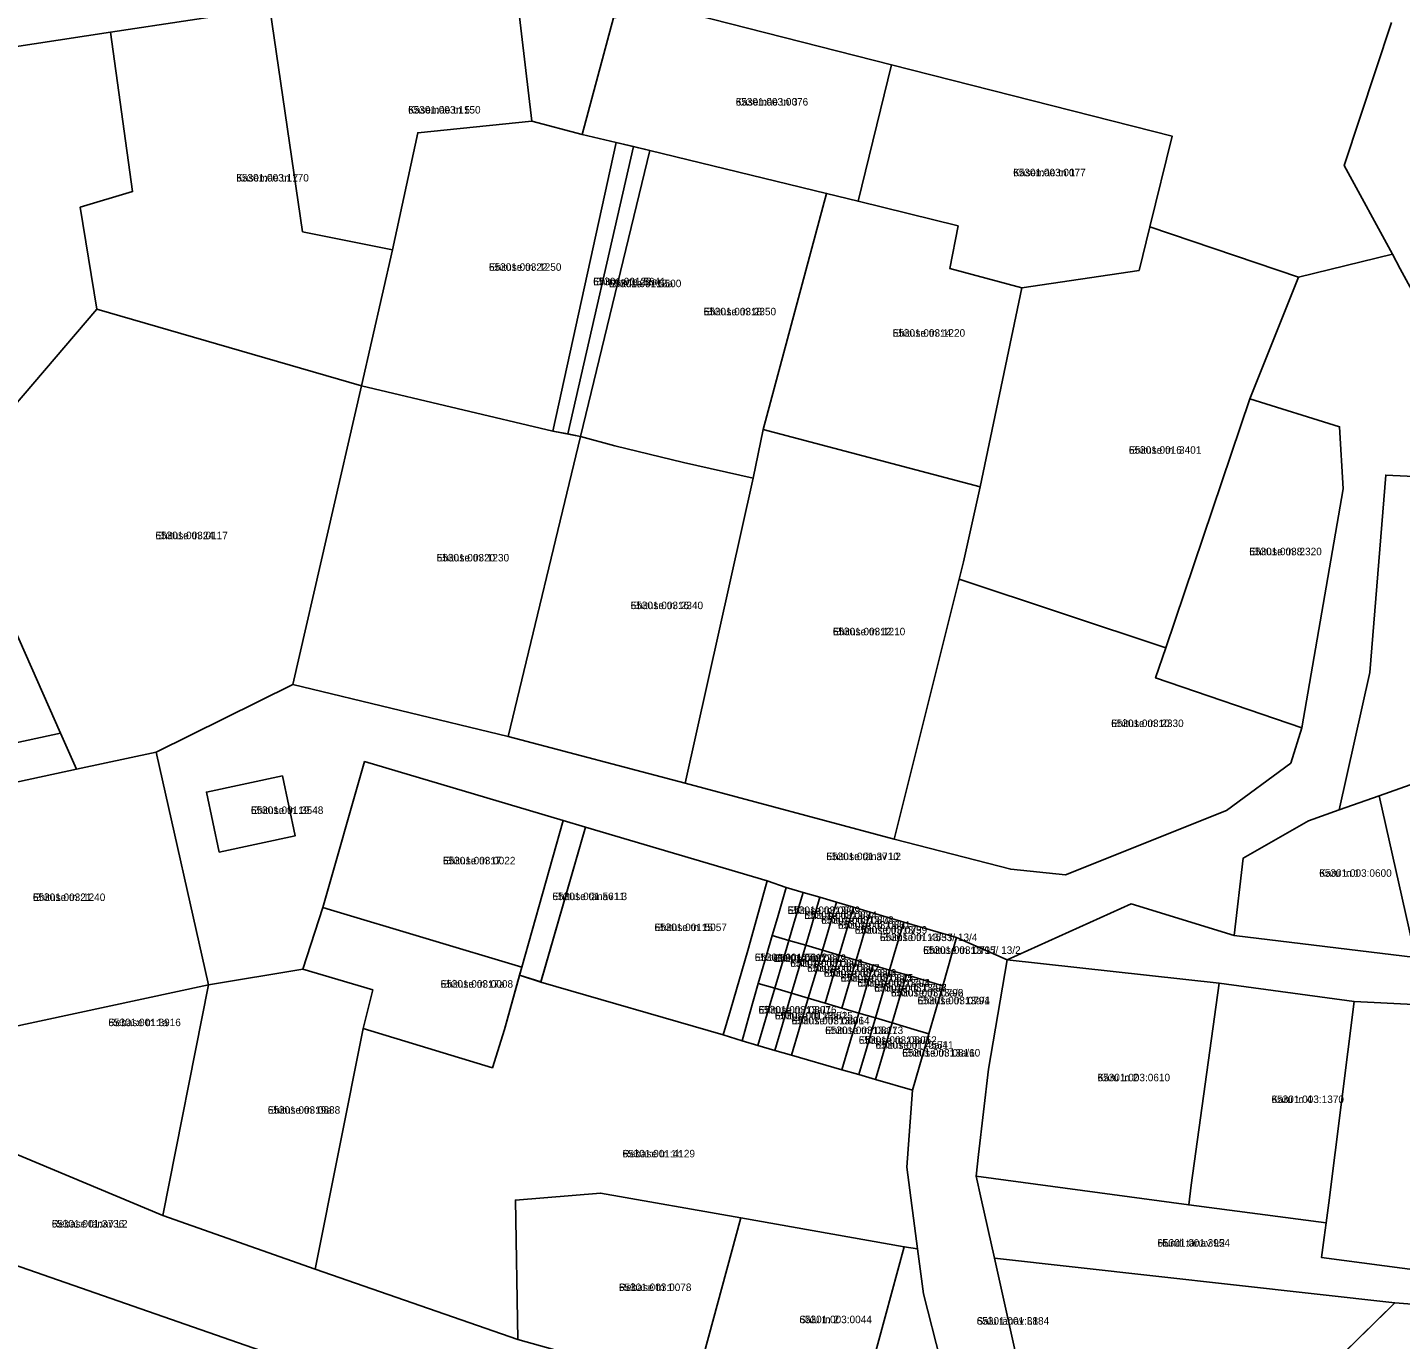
# Model space of a CAD drawing. Extents: x 543236 to 563717, y 6566033 to 6588992.
# Drawn here: x 552009 to 552283.7, y 6580060.9 to 6580323.4 of the extents above; entities that cross this region are included whole.
import ezdxf

# ---------------------------------------------------------------- set-up
doc = ezdxf.new("R2010")
doc.units = 0
for name, color, linetype in [('L_AADRESS', 7, 'Continuous'), ('PIIR', 7, 'Continuous'), ('TUNNUS', 7, 'Continuous')]:
    doc.layers.add(name, color=color, linetype=linetype)

msp = doc.modelspace()

# ---------------------------------------------------------------- linework, layer by layer
at = {"layer": 'PIIR'}
for points in [[(552349.73, 6580335.09), (552347.94, 6580321.84), (552352.5, 6580315.88), (552364.01, 6580312.76), (552367.51, 6580312.26), (552370.38, 6580310.8), (552372.24, 6580309.07), (552376.29, 6580302.8), (552379.06, 6580297.81), (552380.68, 6580293.63), (552380.95, 6580290.94), (552380.67, 6580288.22), (552378.83, 6580283.07), (552376.23, 6580277.67), (552374.34, 6580265.72), (552376.13, 6580261.19), (552353.4, 6580252.76), (552352.01, 6580256.78), (552302.91, 6580239.8), (552283.67, 6580275.08), (552282.1, 6580278.01), (552272.42, 6580295.79), (552281.92, 6580324.33)], [(552126.26, 6580325.27), (552119.98, 6580301.94), (552109.94, 6580304.62), (552106.51, 6580333.43)], [(552057.55, 6580327.21), (552025.67, 6580322.4), (551957.98, 6580312.08)], [(552281.92, 6580324.33), (552272.42, 6580295.79), (552282.1, 6580278.01), (552263.31, 6580273.4), (552233.55, 6580283.52), (552238.01, 6580301.63), (552181.9, 6580315.89), (552138.67, 6580326.89)], [(552302.21, 6580232.83), (552280.76, 6580233.83), (552277.57, 6580194.38), (552271.45, 6580166.87), (552265.28, 6580164.71), (552252.26, 6580157.24), (552250.46, 6580141.78), (552229.81, 6580148.06), (552205.05, 6580136.87), (552194.9, 6580141.33), (552184.33, 6580144.44), (552177.62, 6580146.42), (552174.26, 6580147.41), (552170.9, 6580148.4), (552167.55, 6580149.39), (552164.19, 6580150.38), (552160.83, 6580151.36), (552157.04, 6580152.67), (552120.65, 6580163.41), (552116.18, 6580164.75), (552076.49, 6580176.54), (552068.13, 6580147.34), (552064.15, 6580134.99), (552045.28, 6580131.89), (552034.79, 6580178.45), (552062.11, 6580191.95), (552105.19, 6580181.58), (552140.64, 6580172.21), (552182.43, 6580161.02), (552205.74, 6580155), (552216.71, 6580153.88), (552248.92, 6580166.73), (552261.79, 6580176.25), (552264, 6580183.32), (552272.21, 6580231.07), (552271.53, 6580243.52), (552253.6, 6580249.12), (552263.31, 6580273.4), (552282.1, 6580278.01), (552283.67, 6580275.08), (552302.91, 6580239.8)]]:
    msp.add_lwpolyline(points, dxfattribs=at)
for points in [[(552109.94, 6580304.62), (552087.12, 6580302.32), (552082.05, 6580278.88), (552064.08, 6580282.52), (552057.55, 6580327.21), (552106.51, 6580333.43)], [(552019.62, 6580287.41), (552030.09, 6580290.54), (552025.67, 6580322.4), (552057.55, 6580327.21), (552064.08, 6580282.52), (552082.05, 6580278.88), (552075.9, 6580251.66), (552022.92, 6580267.03)], [(552181.9, 6580315.89), (552175.21, 6580288.61), (552168.91, 6580290.17), (552133.57, 6580298.73), (552126.81, 6580300.37), (552119.98, 6580301.94), (552126.26, 6580325.27), (552138.67, 6580326.89)], [(551957.98, 6580312.08), (552025.67, 6580322.4), (552030.09, 6580290.54), (552019.62, 6580287.41), (552022.92, 6580267.03), (551993.38, 6580232.51)], [(552195.22, 6580283.67), (552175.21, 6580288.61), (552181.9, 6580315.89), (552238.01, 6580301.63), (552233.55, 6580283.52), (552231.4, 6580274.77), (552207.99, 6580271.32), (552193.55, 6580275.19)], [(551849.85, 6580313.46), (551874.55, 6580298.88), (551933.06, 6580166.94), (551943.95, 6580165.14), (551962.55, 6580169.61), (551961.34, 6580174.68), (551989.23, 6580181.38), (551990.34, 6580176.73), (552015.65, 6580182.2), (552018.84, 6580175), (551975.31, 6580165.59), (551976.14, 6580161.48), (551946.3, 6580154.31), (551921.13, 6580148.28), (551915.32, 6580160.99), (551884, 6580229.48)], [(551874.55, 6580298.88), (551957.98, 6580312.08), (551993.38, 6580232.51), (552015.65, 6580182.2), (551990.34, 6580176.73), (551989.23, 6580181.38), (551961.34, 6580174.68), (551962.55, 6580169.61), (551943.95, 6580165.14), (551933.06, 6580166.94)], [(552082.05, 6580278.88), (552087.12, 6580302.32), (552109.94, 6580304.62), (552119.98, 6580301.94), (552126.81, 6580300.37), (552114.11, 6580242.64), (552075.9, 6580251.66)], [(552126.81, 6580300.37), (552130.29, 6580299.53), (552117.13, 6580242.06), (552114.11, 6580242.64)], [(552130.29, 6580299.53), (552133.57, 6580298.73), (552119.69, 6580241.57), (552117.13, 6580242.06)], [(552168.91, 6580290.17), (552156.24, 6580242.97), (552154.2, 6580233.21), (552140.29, 6580236.38), (552126.55, 6580239.72), (552119.69, 6580241.57), (552133.57, 6580298.73)], [(552168.91, 6580290.17), (552175.21, 6580288.61), (552195.22, 6580283.67), (552193.55, 6580275.19), (552207.99, 6580271.32), (552199.64, 6580231.5), (552156.24, 6580242.97)], [(552199.64, 6580231.5), (552207.99, 6580271.32), (552231.4, 6580274.77), (552233.55, 6580283.52), (552263.31, 6580273.4), (552253.6, 6580249.12), (552236.74, 6580199.3), (552195.43, 6580213.02), (552196.26, 6580216.46)], [(552075.9, 6580251.66), (552062.11, 6580191.95), (552034.79, 6580178.45), (552018.84, 6580175), (552015.65, 6580182.2), (551993.38, 6580232.51), (552022.92, 6580267.03)], [(552114.11, 6580242.64), (552119.69, 6580241.57), (552105.19, 6580181.58), (552062.11, 6580191.95), (552075.9, 6580251.66)], [(552236.74, 6580199.3), (552253.6, 6580249.12), (552271.53, 6580243.52), (552272.21, 6580231.07), (552264, 6580183.32), (552234.71, 6580193.29)], [(552119.69, 6580241.57), (552126.55, 6580239.72), (552140.29, 6580236.38), (552154.2, 6580233.21), (552140.64, 6580172.21), (552105.19, 6580181.58)], [(552196.26, 6580216.46), (552182.43, 6580161.02), (552140.64, 6580172.21), (552154.2, 6580233.21), (552156.24, 6580242.97), (552199.64, 6580231.5)], [(552280.76, 6580233.83), (552302.21, 6580232.83), (552309, 6580232.44), (552311.85, 6580225.25), (552326.59, 6580187.27), (552300.31, 6580177.12), (552279.41, 6580169.66), (552271.45, 6580166.87), (552277.57, 6580194.38)], [(552236.74, 6580199.3), (552234.71, 6580193.29), (552264, 6580183.32), (552261.79, 6580176.25), (552248.92, 6580166.73), (552216.71, 6580153.88), (552205.74, 6580155), (552182.43, 6580161.02), (552195.43, 6580213.02)], [(552229.81, 6580148.06), (552250.46, 6580141.78), (552286.73, 6580137.34), (552293.88, 6580137.05), (552313.39, 6580145.17), (552338.95, 6580155.63), (552366.66, 6580169.23), (552388.85, 6580179.25), (552392.05, 6580184.99), (552399.74, 6580178.05), (552372.77, 6580158.12), (552370.94, 6580160.68), (552362.21, 6580156.09), (552377.28, 6580135.24), (552375.31, 6580133.91), (552363.37, 6580132.31), (552351.67, 6580151.11), (552302.99, 6580130.05), (552301.59, 6580129.34), (552296.98, 6580127.42), (552274.44, 6580128.55), (552247.42, 6580132.19), (552205.05, 6580136.87)], [(552045.28, 6580131.89), (551984.75, 6580118.87), (551975.31, 6580165.59), (552018.84, 6580175), (552034.79, 6580178.45)], [(552068.13, 6580147.34), (552076.49, 6580176.54), (552116.18, 6580164.75), (552107.92, 6580135.45), (552069.64, 6580146.9)], [(552293.88, 6580137.05), (552286.73, 6580137.34), (552279.41, 6580169.66), (552300.31, 6580177.12), (552313.39, 6580145.17)], [(552044.86, 6580170.43), (552060.06, 6580173.68), (552062.62, 6580161.7), (552047.41, 6580158.45)], [(552060.06, 6580173.68), (552044.86, 6580170.43), (552047.41, 6580158.45), (552062.62, 6580161.7)], [(552286.73, 6580137.34), (552250.46, 6580141.78), (552252.26, 6580157.24), (552265.28, 6580164.71), (552271.45, 6580166.87), (552279.41, 6580169.66)], [(552107.46, 6580133.79), (552107.92, 6580135.45), (552116.18, 6580164.75), (552120.65, 6580163.41), (552111.77, 6580132.49)], [(551946.3, 6580154.31), (551976.14, 6580161.48), (551984.75, 6580118.87), (552045.28, 6580131.89), (552036.1, 6580085.76), (551979.67, 6580109.38), (551957.98, 6580124.67), (551945.08, 6580146.43)], [(552111.76, 6580132.44), (552120.65, 6580163.41), (552157.04, 6580152.67), (552155.3, 6580146.45), (552153.17, 6580138.75), (552149.67, 6580126.83), (552148.21, 6580121.87)], [(551944.28, 6580097.46), (551921.13, 6580148.28), (551946.3, 6580154.31), (551945.08, 6580146.43), (551957.98, 6580124.67), (551979.67, 6580109.38), (552036.1, 6580085.76), (552066.62, 6580075.05), (552107.12, 6580060.97), (552142.48, 6580051.09), (552174.31, 6580042.16), (552191.6, 6580037.25), (552212.93, 6580030.16), (552231.41, 6580012.4), (552204, 6580013.85), (552177.76, 6580021.91), (552154.81, 6580027.57), (552150.26, 6580025.83), (551965.57, 6580090.06)], [(552149.67, 6580126.83), (552153.17, 6580138.75), (552155.3, 6580146.45), (552157.04, 6580152.67), (552160.83, 6580151.36), (552159.07, 6580145.29), (552158.04, 6580141.76), (552156.89, 6580137.79), (552155.25, 6580132.16), (552153.47, 6580126.03), (552152.02, 6580120.67), (552148.21, 6580121.87)], [(552160.83, 6580151.36), (552164.19, 6580150.38), (552162.43, 6580144.39), (552161.36, 6580140.78), (552158.04, 6580141.76), (552159.07, 6580145.29)], [(552164.19, 6580150.38), (552167.55, 6580149.39), (552165.79, 6580143.41), (552164.72, 6580139.79), (552161.36, 6580140.78), (552162.43, 6580144.39)], [(552078.11, 6580130.87), (552064.15, 6580134.99), (552068.13, 6580147.34), (552069.64, 6580146.9), (552107.92, 6580135.45), (552104.45, 6580122.92), (552102.06, 6580115.29), (552076.23, 6580123.15)], [(552167.55, 6580149.39), (552170.9, 6580148.4), (552169.14, 6580142.42), (552168.08, 6580138.8), (552164.72, 6580139.79), (552165.79, 6580143.41)], [(552170.9, 6580148.4), (552174.26, 6580147.41), (552172.5, 6580141.43), (552171.44, 6580137.82), (552168.08, 6580138.8), (552169.14, 6580142.42)], [(552171.44, 6580137.82), (552172.5, 6580141.43), (552174.26, 6580147.41), (552177.62, 6580146.42), (552175.86, 6580140.44), (552174.79, 6580136.83)], [(552178.15, 6580135.84), (552174.79, 6580136.83), (552175.86, 6580140.44), (552177.62, 6580146.42), (552184.33, 6580144.44), (552182.57, 6580138.46), (552181.51, 6580134.85)], [(552181.51, 6580134.85), (552182.57, 6580138.46), (552184.33, 6580144.44), (552194.9, 6580141.33), (552192.13, 6580131.72), (552184.87, 6580133.86)], [(552158.04, 6580141.76), (552161.36, 6580140.78), (552160.2, 6580136.83), (552158.54, 6580131.19), (552155.25, 6580132.16), (552156.89, 6580137.79)], [(552161.36, 6580140.78), (552164.72, 6580139.79), (552163.56, 6580135.85), (552161.9, 6580130.2), (552158.54, 6580131.19), (552160.2, 6580136.83)], [(552164.72, 6580139.79), (552168.08, 6580138.8), (552166.92, 6580134.87), (552165.25, 6580129.21), (552161.9, 6580130.2), (552163.56, 6580135.85)], [(552191.6, 6580037.25), (552195.07, 6580043.39), (552188.3, 6580070.11), (552187.12, 6580079.07), (552184.94, 6580095.39), (552186.09, 6580110.81), (552189.35, 6580122.11), (552192.13, 6580131.72), (552194.9, 6580141.33), (552205.05, 6580136.87), (552201.29, 6580114.99), (552199.27, 6580097.94), (552198.8, 6580093.63), (552199.82, 6580089.1), (552202.48, 6580077.23), (552212.93, 6580030.16)], [(552168.08, 6580138.8), (552171.44, 6580137.82), (552170.28, 6580133.89), (552168.61, 6580128.22), (552165.25, 6580129.21), (552166.92, 6580134.87)], [(552171.44, 6580137.82), (552174.79, 6580136.83), (552173.64, 6580132.91), (552171.97, 6580127.23), (552168.61, 6580128.22), (552170.28, 6580133.89)], [(552174.79, 6580136.83), (552178.15, 6580135.84), (552177, 6580131.93), (552175.33, 6580126.25), (552171.97, 6580127.23), (552173.64, 6580132.91)], [(552199.27, 6580097.94), (552201.29, 6580114.99), (552205.05, 6580136.87), (552247.42, 6580132.19), (552241.86, 6580091.81), (552241.36, 6580087.86), (552198.8, 6580093.63)], [(552045.28, 6580131.89), (552064.15, 6580134.99), (552078.11, 6580130.87), (552076.23, 6580123.15), (552066.62, 6580075.05), (552036.1, 6580085.76)], [(552066.62, 6580075.05), (552076.23, 6580123.15), (552102.06, 6580115.29), (552104.45, 6580122.92), (552107.46, 6580133.79), (552111.76, 6580132.44), (552148.21, 6580121.87), (552152.02, 6580120.67), (552155.17, 6580119.76), (552158.53, 6580118.78), (552161.9, 6580117.81), (552171.98, 6580114.89), (552175.34, 6580113.92), (552178.71, 6580112.94), (552186.09, 6580110.81), (552184.94, 6580095.39), (552187.12, 6580079.07), (552184.45, 6580079.5), (552151.74, 6580085.28), (552123.71, 6580090.22), (552106.65, 6580088.85), (552107.12, 6580060.97)], [(552178.15, 6580135.84), (552181.51, 6580134.85), (552180.36, 6580130.95), (552178.68, 6580125.26), (552175.33, 6580126.25), (552177, 6580131.93)], [(552181.51, 6580134.85), (552184.87, 6580133.86), (552183.72, 6580129.97), (552182.04, 6580124.27), (552178.68, 6580125.26), (552180.36, 6580130.95)], [(552184.87, 6580133.86), (552192.13, 6580131.72), (552189.35, 6580122.11), (552187.11, 6580122.78), (552182.04, 6580124.27), (552183.72, 6580129.97)], [(552155.25, 6580132.16), (552158.54, 6580131.19), (552156.7, 6580124.94), (552155.17, 6580119.76), (552152.02, 6580120.67), (552153.47, 6580126.03)], [(552158.53, 6580118.78), (552155.17, 6580119.76), (552156.7, 6580124.94), (552158.54, 6580131.19), (552161.9, 6580130.2), (552160.06, 6580123.97)], [(552247.42, 6580132.19), (552274.44, 6580128.55), (552269.35, 6580088.28), (552268.85, 6580084.31), (552241.36, 6580087.86), (552241.86, 6580091.81)], [(552158.53, 6580118.78), (552160.06, 6580123.97), (552161.9, 6580130.2), (552165.25, 6580129.21), (552163.42, 6580122.99), (552161.9, 6580117.81)], [(552161.9, 6580117.81), (552163.42, 6580122.99), (552165.25, 6580129.21), (552168.61, 6580128.22), (552171.97, 6580127.23), (552175.33, 6580126.25), (552173.51, 6580120.07), (552171.98, 6580114.89)], [(552274.44, 6580128.55), (552296.98, 6580127.42), (552301.59, 6580129.34), (552298.56, 6580113.15), (552297.94, 6580082.99), (552296.66, 6580073.52), (552267.93, 6580077.34), (552268.46, 6580081.34), (552268.85, 6580084.31), (552269.35, 6580088.28)], [(552171.98, 6580114.89), (552173.51, 6580120.07), (552175.33, 6580126.25), (552178.68, 6580125.26), (552176.87, 6580119.1), (552175.34, 6580113.92)], [(552178.71, 6580112.94), (552175.34, 6580113.92), (552176.87, 6580119.1), (552178.68, 6580125.26), (552182.04, 6580124.27), (552180.23, 6580118.12)], [(552178.71, 6580112.94), (552180.23, 6580118.12), (552182.04, 6580124.27), (552187.11, 6580122.78), (552189.35, 6580122.11), (552186.09, 6580110.81)], [(552199.82, 6580089.1), (552198.8, 6580093.63), (552241.36, 6580087.86), (552268.85, 6580084.31), (552268.46, 6580081.34), (552267.93, 6580077.34), (552296.66, 6580073.52), (552319.3, 6580071.19), (552318.94, 6580065.41), (552302.33, 6580066.72), (552282.57, 6580068.28), (552202.48, 6580077.23)], [(552064.48, 6579906.03), (551866.39, 6579943.55), (551965.57, 6580090.06), (552150.26, 6580025.83), (552137.47, 6579980.12), (552221.7, 6579960.28), (552236.32, 6579898.67), (552172.64, 6579866.31), (552148, 6579835.36)], [(552123.71, 6580090.22), (552151.74, 6580085.28), (552142.48, 6580051.09), (552107.12, 6580060.97), (552106.65, 6580088.85)], [(552142.48, 6580051.09), (552151.74, 6580085.28), (552184.45, 6580079.5), (552174.31, 6580042.16)], [(552174.31, 6580042.16), (552184.45, 6580079.5), (552187.12, 6580079.07), (552188.3, 6580070.11), (552195.07, 6580043.39), (552191.6, 6580037.25)], [(552282.57, 6580068.28), (552237.03, 6580023.6), (552212.93, 6580030.16), (552202.48, 6580077.23)], [(552282.57, 6580068.28), (552302.33, 6580066.72), (552288.16, 6580010.84), (552237.03, 6580023.6), (552281.29, 6580067.02)]]:
    msp.add_lwpolyline(points, close=True, dxfattribs=at)

# ---------------------------------------------------------------- texts
at = {"layer": 'L_AADRESS'}
for s, p in [('Kasemäe tn 5', (552085.19, 6580306.15)), ('Kasemäe tn 3', (552150.72, 6580307.75)), ('Kasemäe tn 7', (552050.83, 6580292.56)), ('Kasemäe tn 1', (552206.23, 6580293.61)), ('Ehituse tn 22', (552101.36, 6580274.7)), ('Ehituse tn 22a', (552122.2, 6580271.81)), ('Ehituse tn 18a', (552125.35, 6580271.42)), ('Ehituse tn 18', (552144.3, 6580265.8)), ('Ehituse tn 14', (552182.12, 6580261.52)), ('Ehituse tn 6', (552229.37, 6580238.11)), ('Ehituse tn 24', (552034.64, 6580221.02)), ('Ehituse tn 8', (552253.46, 6580217.81)), ('Ehituse tn 20', (552090.9, 6580216.57)), ('Ehituse tn 16', (552129.7, 6580207.03)), ('Ehituse tn 12', (552170.14, 6580201.8)), ('Ehituse tn 10', (552225.83, 6580183.45)), ('Ehituse tn 19', (552053.74, 6580166.07)), ('Ehituse tänav L2', (552168.85, 6580156.83)), ('Ehituse tn 17', (552092.16, 6580155.99)), ('Karu tn 1', (552267.45, 6580153.5)), ('Ehituse tn 21', (552010.12, 6580148.66)), ('Ehituse tänav L3', (552114.05, 6580148.83)), ('Ehituse tn 13/9', (552161.11, 6580146.06)), ('Ehituse tn 13/8', (552164.45, 6580145.08)), ('Ehituse tn 13/7', (552167.81, 6580144.1)), ('Ehituse tn 13/6', (552171.17, 6580143.11)), ('Ehituse tn 15', (552134.47, 6580142.64)), ('Ehituse tn 13/5', (552174.53, 6580142.12)), ('Ehituse tn 13/3 // 13/4', (552179.56, 6580140.64)), ('Ehituse tn 13/1 // 13/2', (552188.21, 6580138.08)), ('Ehituse tn 15a', (552154.52, 6580136.64)), ('Ehituse tn 13a/9', (552158.3, 6580136.47)), ('Ehituse tn 13a/8', (552161.63, 6580135.49)), ('Ehituse tn 13a/7', (552164.99, 6580134.5)), ('Ehituse tn 13a/6', (552168.34, 6580133.51)), ('Ehituse tn 13a/5', (552171.7, 6580132.53)), ('Ehituse tn 17a', (552091.69, 6580131.32)), ('Ehituse tn 13a/4', (552175.06, 6580131.54)), ('Ehituse tn 13a/3', (552178.42, 6580130.55)), ('Ehituse tn 13a/2', (552181.77, 6580129.56)), ('Ehituse tn 13a/1', (552187.09, 6580128)), ('Ehituse tn 13a/16', (552155.28, 6580126.14)), ('Ehituse tn 13a/15', (552158.54, 6580124.98)), ('Ehituse tn 13a/14', (552161.89, 6580123.99)), ('Rebase tn 1a', (552025.23, 6580123.62)), ('Ehituse tn 13a/13', (552168.61, 6580122.04)), ('Ehituse tn 13a/12', (552175.33, 6580120.09)), ('Ehituse tn 13a/11', (552178.69, 6580119.1)), ('Ehituse tn 13a/10', (552184.03, 6580117.54)), ('Karu tn 2', (552223.11, 6580112.6)), ('Karu tn 4', (552257.9, 6580108.25)), ('Ehituse tn 19a', (552057.11, 6580106.11)), ('Rebase tn 1b', (552128.08, 6580097.38)), ('Rebase tänav L2', (552013.9, 6580083.35)), ('Hundi tänav L2', (552235.09, 6580079.52)), ('Rebase tn 1', (552127.37, 6580070.65)), ('Salu tn 2', (552163.46, 6580064.21)), ('Salu tänav L1', (552198.93, 6580063.92))]:
    msp.add_text(s, height=1.5, dxfattribs=at).set_placement(p)
at = {"layer": 'TUNNUS'}
for s, p in [('65301:003:1150', (552085.19, 6580306.15)), ('65301:003:0076', (552150.72, 6580307.75)), ('65301:003:1170', (552050.83, 6580292.56)), ('65301:003:0077', (552206.23, 6580293.61)), ('65301:003:1250', (552101.36, 6580274.7)), ('65301:001:5641', (552122.2, 6580271.81)), ('65301:001:5500', (552125.35, 6580271.42)), ('65301:003:2350', (552144.3, 6580265.8)), ('65301:003:1220', (552182.12, 6580261.52)), ('65301:001:3401', (552229.37, 6580238.11)), ('65301:003:0117', (552034.64, 6580221.02)), ('65301:003:2320', (552253.46, 6580217.81)), ('65301:003:1230', (552090.9, 6580216.57)), ('65301:003:2340', (552129.7, 6580207.03)), ('65301:003:1210', (552170.14, 6580201.8)), ('65301:003:2330', (552225.83, 6580183.45)), ('65301:001:3548', (552053.74, 6580166.07)), ('65301:001:3710', (552168.85, 6580156.83)), ('65301:003:0022', (552092.16, 6580155.99)), ('65301:003:0600', (552267.45, 6580153.5)), ('65301:003:1240', (552010.12, 6580148.66)), ('65301:001:5611', (552114.05, 6580148.83)), ('65301:003:0809', (552161.11, 6580146.06)), ('65301:003:0874', (552164.45, 6580145.08)), ('65301:003:0808', (552167.81, 6580144.1)), ('65301:003:0801', (552171.17, 6580143.11)), ('65301:001:5057', (552134.47, 6580142.64)), ('65301:003:0799', (552174.53, 6580142.12)), ('65301:001:4553', (552179.56, 6580140.64)), ('65301:003:0795', (552188.21, 6580138.08)), ('65301:001:5612', (552154.52, 6580136.64)), ('65301:003:0812', (552158.3, 6580136.47)), ('65301:003:0804', (552161.63, 6580135.49)), ('65301:003:0802', (552164.99, 6580134.5)), ('65301:003:0803', (552168.34, 6580133.51)), ('65301:003:0811', (552171.7, 6580132.53)), ('65301:003:0008', (552091.69, 6580131.32)), ('65301:003:0793', (552175.06, 6580131.54)), ('65301:003:0797', (552178.42, 6580130.55)), ('65301:003:0796', (552181.77, 6580129.56)), ('65301:003:0794', (552187.09, 6580128)), ('65301:003:0807', (552155.28, 6580126.14)), ('65301:001:4552', (552158.54, 6580124.98)), ('65301:003:0806', (552161.89, 6580123.99)), ('65301:001:3916', (552025.23, 6580123.62)), ('65301:003:0817', (552168.61, 6580122.04)), ('65301:003:0805', (552175.33, 6580120.09)), ('65301:001:4554', (552178.69, 6580119.1)), ('65301:003:0816', (552184.03, 6580117.54)), ('65301:003:0610', (552223.11, 6580112.6)), ('65301:003:1370', (552257.9, 6580108.25)), ('65301:003:0838', (552057.11, 6580106.11)), ('65301:001:4129', (552128.08, 6580097.38)), ('65301:001:3736', (552013.9, 6580083.35)), ('65301:001:3954', (552235.09, 6580079.52)), ('65301:003:0078', (552127.37, 6580070.65)), ('65301:003:0044', (552163.46, 6580064.21)), ('65301:001:3884', (552198.93, 6580063.92))]:
    msp.add_text(s, height=1.5, dxfattribs=at).set_placement(p)

doc.saveas('drawing.dxf')
